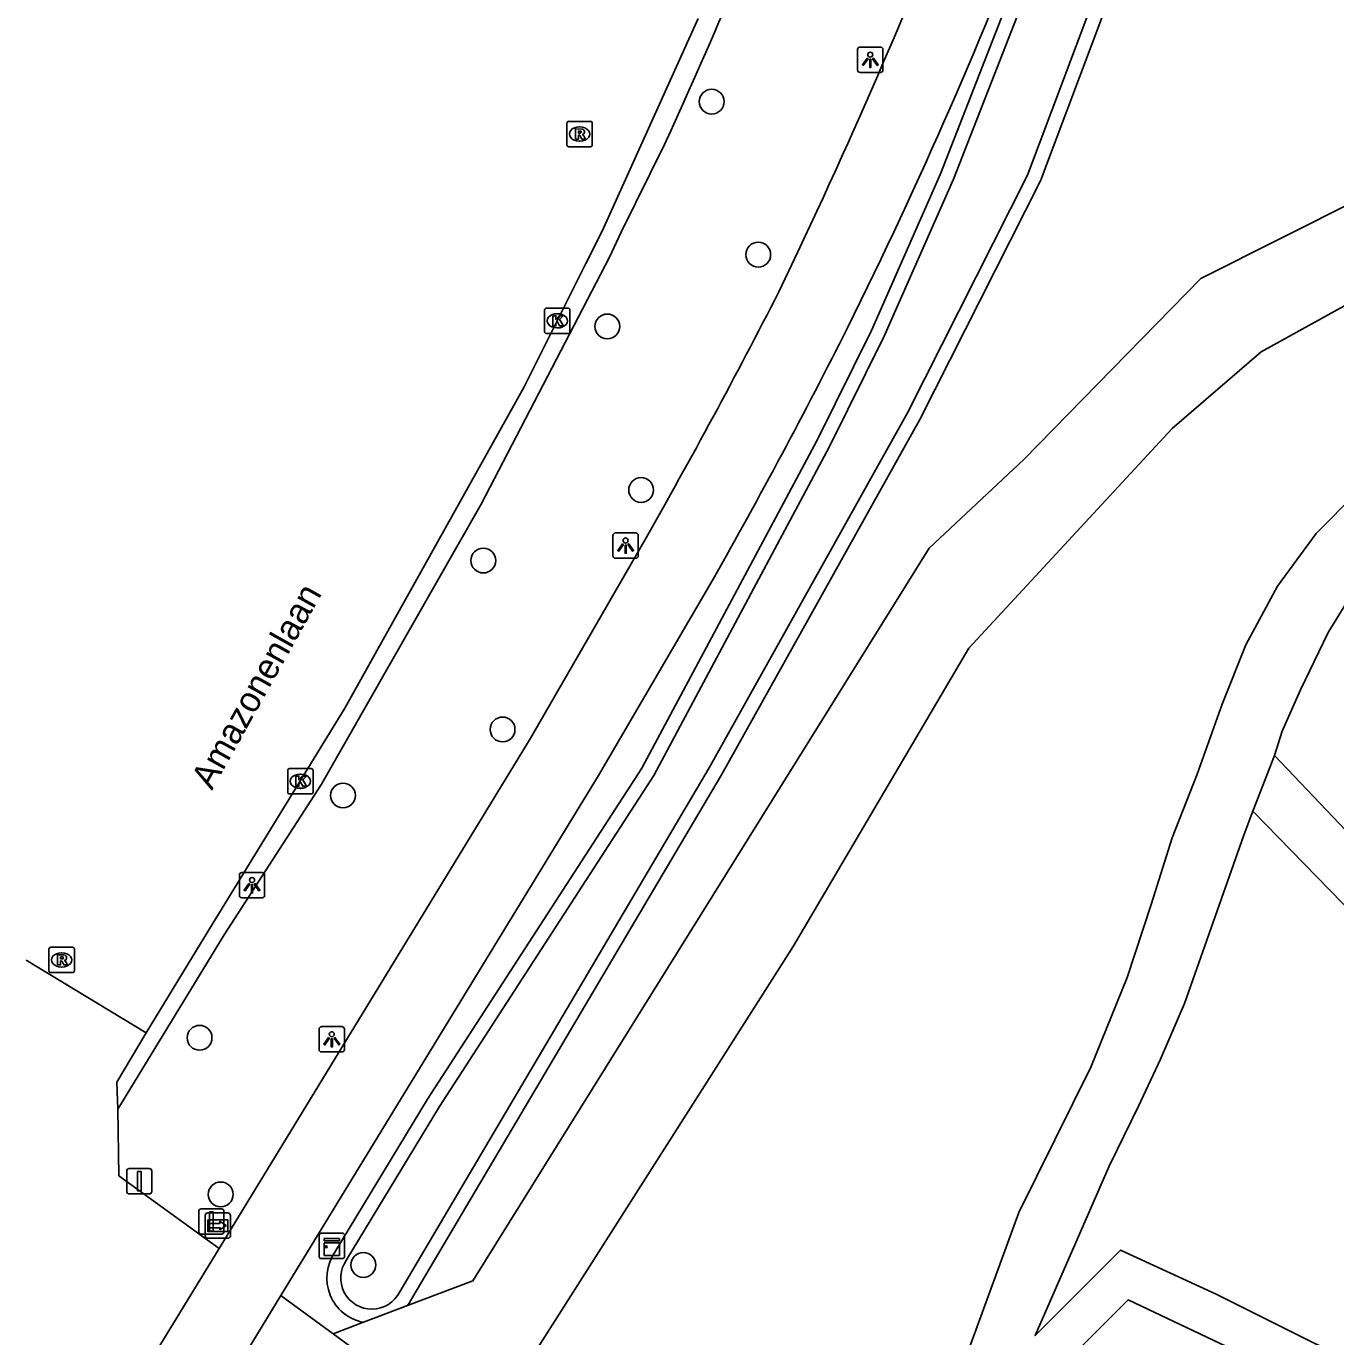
# Model space of a CAD drawing. Extents: x 162791 to 163827, y 385795 to 386523.
# Drawn here: x 162859.8 to 162911.4, y 386058.1 to 386109.7 of the extents above; entities that cross this region are included whole.
import ezdxf

# ---------------------------------------------------------------- set-up
doc = ezdxf.new("R2010")
doc.units = 0
for name, color, linetype in [('IMGEO_Boom', 7, 'Continuous'), ('IMGEO_Fietspad_gesloten', 7, 'Continuous'), ('IMGEO_Groenvoorziening', 7, 'Continuous'), ('IMGEO_Kast', 7, 'Continuous'), ('IMGEO_Kolk', 7, 'Continuous'), ('IMGEO_Lichtpunt', 7, 'Continuous'), ('IMGEO_Openbare_ruimte_label', 7, 'Continuous'), ('IMGEO_Rijbaan_lokaal_gesloten', 7, 'Continuous'), ('IMGEO_Rijbaan_lokaal_open', 7, 'Continuous'), ('IMGEO_Rioolput', 7, 'Continuous'), ('IMGEO_Verkeersbordpaal', 7, 'Continuous'), ('IMGEO_Voetpad_open', 7, 'Continuous'), ('IMGEO_Waterloop', 7, 'Continuous'), ('IMGEO_Wegwijzer', 7, 'Continuous'), ('IMGEO_Woonerf_gesloten', 7, 'Continuous'), ('IMGEO_Woonerf_open', 7, 'Continuous')]:
    doc.layers.add(name, color=color, linetype=linetype)

msp = doc.modelspace()

# ---------------------------------------------------------------- linework, layer by layer
at = {"layer": 'IMGEO_Boom'}
for centre in [(162886.774, 386106.737), (162888.607, 386100.712), (162882.663, 386097.882), (162883.994, 386091.44), (162877.776, 386088.662), (162878.536, 386082.008), (162872.249, 386079.408), (162866.6, 386069.865), (162867.433, 386063.695), (162873.051, 386060.918)]:
    msp.add_circle(centre, 0.489, dxfattribs=at)
at = {"layer": 'IMGEO_Fietspad_gesloten'}
for points in [[(162884.137, 386089.47), (162879.623, 386081.646), (162867.368, 386061.567)], [(162869.806, 386059.708), (162882.31, 386080.195), (162886.828, 386087.923)], [(162866.596, 386054.448), (162869.806, 386059.708)]]:
    msp.add_lwpolyline(points, dxfattribs=at)
for centre, radius, start, end in [((162659.063, 386209.733), 255.482, 334.37444, 338.57894), ((162717.543, 386184.554), 194.934, 333.58344, 339.20108), ((162670.339, 386211.28), 246.064, 330.32802, 332.91391), ((162683.634, 386202.903), 233.47, 330.49601, 333.2528)]:
    msp.add_arc(centre, radius, start, end, dxfattribs=at)
at = {"layer": 'IMGEO_Groenvoorziening'}
for points in [[(162905.141, 386127.836), (162895.786, 386103.895), (162893.07, 386097.727), (162890.922, 386093.403), (162884.024, 386080.479), (162875.581, 386067.445), (162871.933, 386061.417)], [(162874.791, 386059.317), (162874.855, 386059.406), (162874.913, 386059.498), (162874.965, 386059.593), (162887.154, 386080.222), (162894.974, 386094.22), (162899.723, 386103.62), (162907.863, 386125.267)]]:
    msp.add_lwpolyline(points, dxfattribs=at)
msp.add_arc((162873.387, 386060.401), 1.774, 145.0413, 259.2188, dxfattribs=at)
at = {"layer": 'IMGEO_Kast'}
for p, q in [((162871.314, 386061.243), (162871.314, 386062.084)), ((162871.314, 386062.084), (162871.314, 386061.243)), ((162871.389, 386062.168), (162872.23, 386062.168)), ((162872.23, 386062.168), (162871.389, 386062.168)), ((162872.314, 386062.093), (162872.314, 386061.252)), ((162872.314, 386061.252), (162872.314, 386062.093)), ((162872.239, 386061.168), (162871.398, 386061.168)), ((162871.398, 386061.168), (162872.239, 386061.168))]:
    msp.add_line(p, q, dxfattribs=at)
for points in [[(162871.509, 386061.958), (162872.109, 386061.958), (162872.109, 386061.873), (162871.509, 386061.873), (162871.509, 386061.958)], [(162871.509, 386061.783), (162872.109, 386061.783), (162872.109, 386061.294), (162871.509, 386061.294), (162871.509, 386061.783)]]:
    msp.add_lwpolyline(points, dxfattribs=at)
msp.add_circle((162871.593, 386061.632), 0.0377, dxfattribs=at)
for centre, start, end in [((162871.392, 386062.09), 92.4484, 184.2845), ((162871.392, 386062.09), 92.4484, 184.2845), ((162872.236, 386062.09), 2.4484, 94.2845), ((162872.236, 386062.09), 2.4484, 94.2845), ((162871.392, 386061.246), 182.4484, 274.2845), ((162871.392, 386061.246), 182.4484, 274.2845), ((162872.236, 386061.246), 272.4484, 4.2845), ((162872.236, 386061.246), 272.4484, 4.2845)]:
    msp.add_arc(centre, 0.0779, start, end, dxfattribs=at)
at = {"layer": 'IMGEO_Kolk'}
for p, q in [((162880.19, 386097.678), (162880.19, 386098.53)), ((162880.265, 386098.604), (162881.117, 386098.604)), ((162881.191, 386098.53), (162881.191, 386097.678)), ((162880.678, 386098.384), (162880.703, 386098.384)), ((162881.117, 386097.604), (162880.265, 386097.604)), ((162880.701, 386097.824), (162880.676, 386097.824)), ((162870.147, 386080.47), (162870.999, 386080.47)), ((162870.072, 386079.544), (162870.072, 386080.396)), ((162870.56, 386080.25), (162870.585, 386080.25)), ((162871.073, 386080.396), (162871.073, 386079.544)), ((162870.999, 386079.47), (162870.147, 386079.47)), ((162870.583, 386079.69), (162870.558, 386079.69))]:
    msp.add_line(p, q, dxfattribs=at)
for points in [[(162880.19, 386097.678), (162880.19, 386098.53)], [(162880.265, 386098.604), (162881.117, 386098.604)], [(162881.191, 386098.53), (162881.191, 386097.678)], [(162880.511, 386098.304), (162880.634, 386098.304), (162880.634, 386098.153), (162880.764, 386098.304), (162880.928, 386098.304), (162880.782, 386098.153), (162880.935, 386097.904), (162880.783, 386097.904), (162880.698, 386098.068), (162880.634, 386098.001), (162880.634, 386097.904), (162880.511, 386097.904), (162880.511, 386098.304)], [(162881.117, 386097.604), (162880.265, 386097.604)], [(162870.147, 386080.47), (162870.999, 386080.47)], [(162870.072, 386079.544), (162870.072, 386080.396)], [(162870.393, 386080.17), (162870.516, 386080.17), (162870.516, 386080.019), (162870.646, 386080.17), (162870.81, 386080.17), (162870.664, 386080.019), (162870.817, 386079.77), (162870.665, 386079.77), (162870.58, 386079.934), (162870.516, 386079.867), (162870.516, 386079.77), (162870.393, 386079.77), (162870.393, 386080.17)], [(162871.073, 386080.396), (162871.073, 386079.544)], [(162870.999, 386079.47), (162870.147, 386079.47)]]:
    msp.add_lwpolyline(points, dxfattribs=at)
for centre, start, end in [((162880.267, 386098.528), 91.552, 178.448), ((162880.267, 386098.528), 91.552, 178.448), ((162881.115, 386098.528), 1.552, 88.448), ((162881.115, 386098.528), 1.552, 88.448), ((162880.267, 386097.68), 181.552, 268.448), ((162880.267, 386097.68), 181.552, 268.448), ((162881.115, 386097.68), 271.552, 358.448), ((162881.115, 386097.68), 271.552, 358.448), ((162870.149, 386080.394), 91.552, 178.448), ((162870.149, 386080.394), 91.552, 178.448), ((162870.997, 386080.394), 1.552, 88.448), ((162870.997, 386080.394), 1.552, 88.448), ((162870.149, 386079.546), 181.552, 268.448), ((162870.149, 386079.546), 181.552, 268.448), ((162870.997, 386079.546), 271.552, 358.448), ((162870.997, 386079.546), 271.552, 358.448)]:
    msp.add_arc(centre, 0.0765, start, end, dxfattribs=at)
for centre, major_axis, ratio, start_param, end_param in [((162880.677, 386098.104), (-0.387, 0.002), 0.722429, 4.712389, 7.853982), ((162880.702, 386098.104), (-0.39, 0.002), 0.717154, 1.570796, 4.712389), ((162870.559, 386079.97), (-0.387, 0.002), 0.722429, 4.712389, 7.853982), ((162870.584, 386079.97), (-0.39, 0.002), 0.717154, 1.570796, 4.712389)]:
    msp.add_ellipse(centre, major_axis=major_axis, ratio=ratio, start_param=start_param, end_param=end_param, dxfattribs=at)
at = {"layer": 'IMGEO_Lichtpunt'}
for p, q in [((162893.423, 386108.884), (162892.615, 386108.884)), ((162893.423, 386108.884), (162892.615, 386108.884)), ((162892.521, 386108.789), (162892.521, 386107.982)), ((162892.521, 386108.789), (162892.521, 386107.982)), ((162893.517, 386107.982), (162893.517, 386108.789)), ((162893.517, 386107.982), (162893.517, 386108.789)), ((162892.615, 386107.888), (162893.423, 386107.888)), ((162892.615, 386107.888), (162893.423, 386107.888)), ((162883.787, 386089.748), (162882.979, 386089.748)), ((162883.787, 386089.748), (162882.979, 386089.748)), ((162882.885, 386089.653), (162882.885, 386088.846)), ((162882.885, 386089.653), (162882.885, 386088.846)), ((162883.881, 386088.846), (162883.881, 386089.653)), ((162883.881, 386088.846), (162883.881, 386089.653)), ((162882.979, 386088.752), (162883.787, 386088.752)), ((162882.979, 386088.752), (162883.787, 386088.752)), ((162869.07, 386076.373), (162868.262, 386076.373)), ((162869.07, 386076.373), (162868.262, 386076.373)), ((162868.168, 386076.278), (162868.168, 386075.471)), ((162868.168, 386076.278), (162868.168, 386075.471)), ((162869.164, 386075.471), (162869.164, 386076.278)), ((162869.164, 386075.471), (162869.164, 386076.278)), ((162868.262, 386075.377), (162869.07, 386075.377)), ((162868.262, 386075.377), (162869.07, 386075.377)), ((162871.31, 386070.208), (162871.31, 386069.401)), ((162871.31, 386070.208), (162871.31, 386069.401)), ((162872.212, 386070.303), (162871.404, 386070.303)), ((162872.212, 386070.303), (162871.404, 386070.303)), ((162872.306, 386069.401), (162872.306, 386070.208)), ((162872.306, 386069.401), (162872.306, 386070.208)), ((162871.404, 386069.307), (162872.212, 386069.307)), ((162871.404, 386069.307), (162872.212, 386069.307))]:
    msp.add_line(p, q, dxfattribs=at)
for points in [[(162892.895, 386108.453), (162892.934, 386108.425), (162892.746, 386108.163), (162892.708, 386108.19), (162892.895, 386108.453)], [(162892.997, 386108.405), (162893.044, 386108.405), (162893.044, 386108.083), (162892.997, 386108.083), (162892.997, 386108.405)], [(162893.107, 386108.425), (162893.145, 386108.452), (162893.332, 386108.19), (162893.293, 386108.162), (162893.107, 386108.425)], [(162883.259, 386089.317), (162883.298, 386089.289), (162883.11, 386089.027), (162883.072, 386089.054), (162883.259, 386089.317)], [(162883.361, 386089.269), (162883.408, 386089.269), (162883.408, 386088.947), (162883.361, 386088.947), (162883.361, 386089.269)], [(162883.471, 386089.289), (162883.509, 386089.316), (162883.696, 386089.054), (162883.657, 386089.026), (162883.471, 386089.289)], [(162868.542, 386075.942), (162868.581, 386075.914), (162868.393, 386075.652), (162868.355, 386075.679), (162868.542, 386075.942)], [(162868.644, 386075.894), (162868.691, 386075.894), (162868.691, 386075.572), (162868.644, 386075.572), (162868.644, 386075.894)], [(162868.754, 386075.914), (162868.792, 386075.941), (162868.979, 386075.679), (162868.94, 386075.651), (162868.754, 386075.914)], [(162871.684, 386069.872), (162871.723, 386069.844), (162871.535, 386069.582), (162871.497, 386069.609), (162871.684, 386069.872)], [(162871.786, 386069.824), (162871.833, 386069.824), (162871.833, 386069.502), (162871.786, 386069.502), (162871.786, 386069.824)], [(162871.896, 386069.844), (162871.934, 386069.871), (162872.121, 386069.609), (162872.082, 386069.581), (162871.896, 386069.844)]]:
    msp.add_lwpolyline(points, dxfattribs=at)
for centre in [(162893.02, 386108.587), (162883.384, 386089.451), (162868.667, 386076.076), (162871.809, 386070.006)]:
    msp.add_circle(centre, 0.0994, dxfattribs=at)
for centre, start, end in [((162892.615, 386108.789), 90, 180), ((162892.615, 386108.789), 90, 180), ((162893.423, 386108.789), 0, 90), ((162893.423, 386108.789), 0, 90), ((162892.615, 386107.982), 180, 270), ((162892.615, 386107.982), 180, 270), ((162893.423, 386107.982), 270, 0), ((162893.423, 386107.982), 270, 360), ((162882.979, 386089.653), 90, 180), ((162882.979, 386089.653), 90, 180), ((162883.787, 386089.653), 0, 90), ((162883.787, 386089.653), 0, 90), ((162882.979, 386088.846), 180, 270), ((162882.979, 386088.846), 180, 270), ((162883.787, 386088.846), 270, 0), ((162883.787, 386088.846), 270, 360), ((162868.262, 386076.278), 90, 180), ((162868.262, 386076.278), 90, 180), ((162869.07, 386076.278), 0, 90), ((162869.07, 386076.278), 0, 90), ((162868.262, 386075.471), 180, 270), ((162868.262, 386075.471), 180, 270), ((162869.07, 386075.471), 270, 0), ((162869.07, 386075.471), 270, 360), ((162871.404, 386070.208), 90, 180), ((162871.404, 386070.208), 90, 180), ((162872.212, 386070.208), 0, 90), ((162872.212, 386070.208), 0, 90), ((162871.404, 386069.401), 180, 270), ((162871.404, 386069.401), 180, 270), ((162872.212, 386069.401), 270, 0), ((162872.212, 386069.401), 270, 360)]:
    msp.add_arc(centre, 0.0946, start, end, dxfattribs=at)
at = {"layer": 'IMGEO_Rijbaan_lokaal_gesloten'}
msp.add_lwpolyline([(162864.499, 386070.058), (162866.989, 386074.154), (162872.319, 386082.845), (162879.372, 386095.475), (162881.82, 386100.356), (162882.465, 386101.636), (162886.236, 386110.011)], dxfattribs=at)
at = {"layer": 'IMGEO_Rijbaan_lokaal_open'}
for points in [[(162864.499, 386070.058), (162859.772, 386072.924), (162859.772, 386072.924)], [(162863.384, 386067.049), (162863.345, 386068.122), (162864.499, 386070.058)], [(162867.368, 386061.567), (162863.415, 386064.433), (162863.384, 386067.049)], [(162863.779, 386055.688), (162867.368, 386061.567)]]:
    msp.add_lwpolyline(points, dxfattribs=at)
at = {"layer": 'IMGEO_Rioolput'}
for p, q in [((162881.068, 386105.035), (162881.068, 386105.887)), ((162881.143, 386105.961), (162881.995, 386105.961)), ((162881.556, 386105.741), (162881.581, 386105.741)), ((162882.069, 386105.887), (162882.069, 386105.035)), ((162881.995, 386104.961), (162881.143, 386104.961)), ((162881.579, 386105.181), (162881.554, 386105.181)), ((162860.667, 386072.506), (162860.667, 386073.358)), ((162860.742, 386073.432), (162861.594, 386073.432)), ((162861.155, 386073.212), (162861.18, 386073.212)), ((162861.668, 386073.358), (162861.668, 386072.506)), ((162861.594, 386072.432), (162860.742, 386072.432)), ((162861.178, 386072.652), (162861.153, 386072.652))]:
    msp.add_line(p, q, dxfattribs=at)
for points in [[(162881.068, 386105.035), (162881.068, 386105.887)], [(162881.143, 386105.961), (162881.995, 386105.961)], [(162882.069, 386105.887), (162882.069, 386105.035)], [(162881.657, 386105.659), (162881.405, 386105.661), (162881.405, 386105.261)], [(162881.405, 386105.261), (162881.529, 386105.261), (162881.529, 386105.423), (162881.54, 386105.423)], [(162881.583, 386105.58), (162881.529, 386105.58), (162881.529, 386105.499)], [(162881.529, 386105.499), (162881.581, 386105.499)], [(162881.587, 386105.394), (162881.658, 386105.261), (162881.798, 386105.261), (162881.733, 386105.387)], [(162881.995, 386104.961), (162881.143, 386104.961)], [(162860.667, 386072.506), (162860.667, 386073.358)], [(162860.742, 386073.432), (162861.594, 386073.432)], [(162861.668, 386073.358), (162861.668, 386072.506)], [(162861.256, 386073.13), (162861.004, 386073.132), (162861.004, 386072.732)], [(162861.004, 386072.732), (162861.128, 386072.732), (162861.128, 386072.894), (162861.139, 386072.894)], [(162861.182, 386073.051), (162861.128, 386073.051), (162861.128, 386072.97)], [(162861.128, 386072.97), (162861.18, 386072.97)], [(162861.186, 386072.865), (162861.257, 386072.732), (162861.397, 386072.732), (162861.332, 386072.858)], [(162861.594, 386072.432), (162860.742, 386072.432)]]:
    msp.add_lwpolyline(points, dxfattribs=at)
for centre, radius, start, end in [((162881.145, 386105.885), 0.0765, 91.552, 178.448), ((162881.145, 386105.885), 0.0765, 91.552, 178.448), ((162881.993, 386105.885), 0.0765, 1.552, 88.448), ((162881.993, 386105.885), 0.0765, 1.552, 88.448), ((162881.539, 386105.37), 0.0533, 26.0293, 88.6989), ((162881.565, 386105.688), 0.19, 274.7715, 282.9687), ((162881.589, 386105.484), 0.0964, 77.0061, 93.1865), ((162881.603, 386105.541), 0.0378, 276.6634, 79.6772), ((162881.656, 386105.549), 0.109, 350.3612, 89.416), ((162881.654, 386105.549), 0.112, 277.5842, 350.9817), ((162881.638, 386105.334), 0.108, 29.5134, 73.7905), ((162881.145, 386105.037), 0.0765, 181.552, 268.448), ((162881.145, 386105.037), 0.0765, 181.552, 268.448), ((162881.993, 386105.037), 0.0765, 271.552, 358.448), ((162881.993, 386105.037), 0.0765, 271.552, 358.448), ((162860.744, 386073.356), 0.0765, 91.552, 178.448), ((162860.744, 386073.356), 0.0765, 91.552, 178.448), ((162861.592, 386073.356), 0.0765, 1.552, 88.448), ((162861.592, 386073.356), 0.0765, 1.552, 88.448), ((162861.138, 386072.841), 0.0533, 26.0293, 88.6989), ((162861.164, 386073.159), 0.19, 274.7715, 282.9687), ((162861.188, 386072.955), 0.0964, 77.0061, 93.1865), ((162861.202, 386073.012), 0.0378, 276.6634, 79.6772), ((162861.255, 386073.02), 0.109, 350.3612, 89.416), ((162861.253, 386073.02), 0.112, 277.5842, 350.9817), ((162861.237, 386072.805), 0.108, 29.5134, 73.7905), ((162860.744, 386072.508), 0.0765, 181.552, 268.448), ((162860.744, 386072.508), 0.0765, 181.552, 268.448), ((162861.592, 386072.508), 0.0765, 271.552, 358.448), ((162861.592, 386072.508), 0.0765, 271.552, 358.448)]:
    msp.add_arc(centre, radius, start, end, dxfattribs=at)
for centre, major_axis, ratio, start_param, end_param in [((162881.555, 386105.461), (-0.387, 0.002), 0.722429, 4.712389, 7.853982), ((162881.58, 386105.461), (-0.39, 0.002), 0.717154, 1.570796, 4.712389), ((162861.154, 386072.932), (-0.387, 0.002), 0.722429, 4.712389, 7.853982), ((162861.179, 386072.932), (-0.39, 0.002), 0.717154, 1.570796, 4.712389)]:
    msp.add_ellipse(centre, major_axis=major_axis, ratio=ratio, start_param=start_param, end_param=end_param, dxfattribs=at)
at = {"layer": 'IMGEO_Verkeersbordpaal'}
for p, q in [((162863.731, 386063.817), (162863.731, 386064.617)), ((162863.731, 386064.617), (162863.731, 386063.817)), ((162863.831, 386064.717), (162864.621, 386064.717)), ((162864.621, 386064.717), (162863.831, 386064.717)), ((162864.721, 386064.617), (162864.721, 386063.817)), ((162864.721, 386063.817), (162864.721, 386064.617)), ((162864.621, 386063.717), (162863.831, 386063.717)), ((162863.831, 386063.717), (162864.621, 386063.717)), ((162866.569, 386062.229), (162866.569, 386063.029)), ((162866.569, 386063.029), (162866.569, 386062.229)), ((162866.669, 386063.129), (162867.459, 386063.129)), ((162867.459, 386063.129), (162866.669, 386063.129)), ((162867.559, 386063.029), (162867.559, 386062.229)), ((162867.559, 386062.229), (162867.559, 386063.029)), ((162867.459, 386062.129), (162866.669, 386062.129)), ((162866.669, 386062.129), (162867.459, 386062.129))]:
    msp.add_line(p, q, dxfattribs=at)
for points in [[(162864.151, 386064.592), (162864.301, 386064.592), (162864.301, 386063.842), (162864.151, 386063.842), (162864.151, 386064.592)], [(162866.989, 386063.004), (162867.139, 386063.004), (162867.139, 386062.254), (162866.989, 386062.254), (162866.989, 386063.004)]]:
    msp.add_lwpolyline(points, dxfattribs=at)
for centre, start, end in [((162863.831, 386064.617), 90, 180), ((162863.831, 386064.617), 90, 180), ((162864.621, 386064.617), 0, 90), ((162864.621, 386064.617), 360, 90), ((162863.831, 386063.817), 180, 270), ((162863.831, 386063.817), 180, 270), ((162864.621, 386063.817), 270, 0), ((162864.621, 386063.817), 270, 0), ((162866.669, 386063.029), 90, 180), ((162866.669, 386063.029), 90, 180), ((162867.459, 386063.029), 0, 90), ((162867.459, 386063.029), 360, 90), ((162866.669, 386062.229), 180, 270), ((162866.669, 386062.229), 180, 270), ((162867.459, 386062.229), 270, 0), ((162867.459, 386062.229), 270, 0)]:
    msp.add_arc(centre, 0.1, start, end, dxfattribs=at)
at = {"layer": 'IMGEO_Voetpad_open'}
for points in [[(162863.384, 386067.049), (162867.572, 386073.915), (162871.409, 386079.854), (162877.694, 386090.889), (162882.742, 386100.615), (162883.213, 386101.598), (162884.918, 386105.052)], [(162908.938, 386080.983), (162915.594, 386073.987), (162914.145, 386072.584), (162908.085, 386078.794)], [(162908.085, 386078.794), (162908.938, 386080.983)]]:
    msp.add_lwpolyline(points, dxfattribs=at)
msp.add_arc((162691.006, 386194.201), 213.423, 335.30995, 345.30194, dxfattribs=at)
at = {"layer": 'IMGEO_Waterloop'}
for points in [[(162905.643, 386127.61), (162896.294, 386103.684), (162893.568, 386097.494), (162891.411, 386093.151), (162884.498, 386080.2), (162876.047, 386067.153), (162872.393, 386061.115)], [(162894.489, 386094.478), (162899.219, 386103.841), (162907.344, 386125.448)], [(162874.483, 386059.857), (162886.678, 386080.496), (162894.489, 386094.478)]]:
    msp.add_lwpolyline(points, dxfattribs=at)
msp.add_arc((162873.386, 386060.4), 1.224, 144.2314, 333.68, dxfattribs=at)
at = {"layer": 'IMGEO_Wegwijzer'}
for p, q in [((162866.923, 386062.969), (162867.713, 386062.969)), ((162867.713, 386062.969), (162866.923, 386062.969)), ((162866.823, 386062.069), (162866.823, 386062.869)), ((162866.823, 386062.869), (162866.823, 386062.069)), ((162867.813, 386062.869), (162867.813, 386062.069)), ((162867.813, 386062.069), (162867.813, 386062.869)), ((162867.713, 386061.969), (162866.923, 386061.969)), ((162866.923, 386061.969), (162867.713, 386061.969))]:
    msp.add_line(p, q, dxfattribs=at)
for points in [[(162866.924, 386062.701), (162867.712, 386062.701), (162867.712, 386062.237), (162866.924, 386062.237), (162866.924, 386062.701)], [(162866.989, 386062.553), (162866.989, 386062.469), (162866.989, 386062.385), (162867.4, 386062.385), (162867.4, 386062.302), (162867.647, 386062.469), (162867.4, 386062.636), (162867.4, 386062.553), (162866.989, 386062.553)]]:
    msp.add_lwpolyline(points, dxfattribs=at)
for centre, start, end in [((162866.923, 386062.869), 90, 180), ((162866.923, 386062.869), 90, 180), ((162867.713, 386062.869), 0, 90), ((162867.713, 386062.869), 360, 90), ((162866.923, 386062.069), 180, 270), ((162866.923, 386062.069), 180, 270), ((162867.713, 386062.069), 270, 0), ((162867.713, 386062.069), 270, 0)]:
    msp.add_arc(centre, 0.1, start, end, dxfattribs=at)
at = {"layer": 'IMGEO_Woonerf_gesloten'}
for points in [[(162912.191, 386091.347), (162910.59, 386089.723), (162909.061, 386087.648), (162907.811, 386085.338), (162906.885, 386083.002), (162905.897, 386080.251), (162904.913, 386077.744), (162904.079, 386075.111), (162903.136, 386072.245), (162901.706, 386068.713), (162898.872, 386062.985), (162896.29, 386055.904), (162895.313, 386054.285), (162894.777, 386053.602), (162894.087, 386052.95), (162892.208, 386051.183), (162888.963, 386047.799), (162887.245, 386046.272)], [(162911.788, 386087.028), (162911.062, 386085.833), (162909.961, 386083.574), (162909.245, 386081.939), (162908.938, 386080.983)], [(162908.085, 386078.794), (162907.738, 386077.852), (162905.396, 386071.212), (162904.448, 386069.029), (162903.588, 386067.177), (162902.433, 386064.802), (162901.305, 386062.228), (162899.512, 386058.136), (162902.875, 386061.502), (162906.638, 386059.762), (162914.557, 386055.812), (162919.493, 386053.551)], [(162871.857, 386058.203), (162869.96, 386059.595), (162869.806, 386059.708)], [(162898.426, 386054.785), (162903.176, 386059.54), (162908.078, 386057.219), (162913.088, 386054.646), (162918.26, 386052.067), (162918.699, 386051.778)], [(162871.857, 386058.203), (162878.872, 386053.053)]]:
    msp.add_lwpolyline(points, dxfattribs=at)
at = {"layer": 'IMGEO_Woonerf_open'}
for points in [[(162924.209, 386109.405), (162912.338, 386102.938), (162906.04, 386099.773), (162899.073, 386092.639), (162895.333, 386089.156), (162877.368, 386060.296), (162874.791, 386059.317)], [(162925.793, 386106.483), (162908.415, 386096.881), (162904.907, 386093.859), (162896.908, 386085.212), (162889.984, 386073.464), (162879.935, 386057.678), (162878.872, 386053.053)], [(162874.791, 386059.317), (162873.055, 386058.658)], [(162873.055, 386058.658), (162871.857, 386058.203)]]:
    msp.add_lwpolyline(points, dxfattribs=at)

# ---------------------------------------------------------------- texts
at = {"layer": 'IMGEO_Openbare_ruimte_label'}
msp.add_text('Amazonenlaan', height=1, rotation=60.7952, dxfattribs=at).set_placement((162867.088, 386079.585))

doc.saveas('drawing.dxf')
